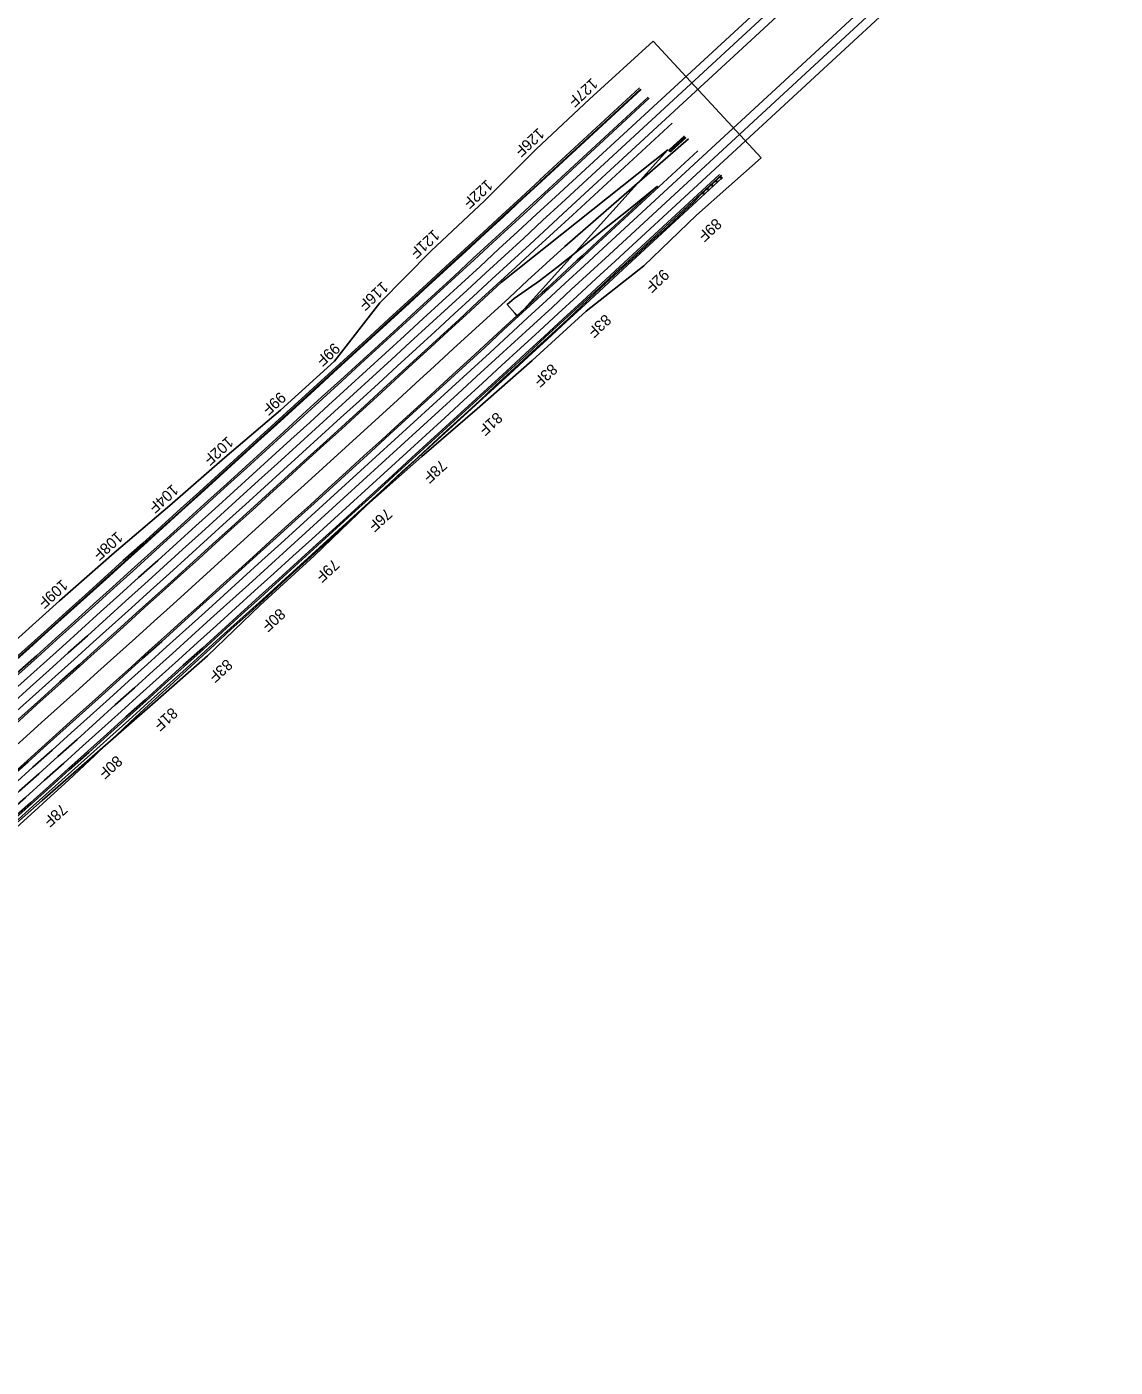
# Model space of a CAD drawing. Extents: x 2163396 to 2173129, y 605545 to 614595.
# Drawn here: x 2170912 to 2172401, y 611661 to 613496 of the extents above; entities that cross this region are included whole.
import ezdxf

# ---------------------------------------------------------------- set-up
doc = ezdxf.new("R2010")
doc.units = 0
for name, color, linetype in [('RD_PD_AsphRem', 7, 'Continuous'), ('RD_PD_CstnLmt', 7, 'Continuous'), ('RD_PD_EarthShd', 7, 'Continuous'), ('RD_PD_Final_LnLine', 7, 'Continuous'), ('RD_PD_Final_TrvlWay', 7, 'Continuous'), ('RD_PD_GR', 7, 'Continuous'), ('RD_PD_MedBWall', 7, 'Continuous'), ('RD_PD_MedGR', 7, 'Continuous'), ('RD_PD_TX_CstnLmt', 7, 'Continuous')]:
    doc.layers.add(name, color=color, linetype=linetype)

msp = doc.modelspace()

# ---------------------------------------------------------------- linework, layer by layer
at = {"layer": 'RD_PD_AsphRem'}
for p, q in [((2171692.3, 613201.6), (2171774.8, 613277.7)), ((2171839.8, 613272.5), (2171724.9, 613166.3))]:
    msp.add_line(p, q, dxfattribs=at)
for points in [[(2171774.8, 613277.7), (2171737.4, 613247.4), (2171702.4, 613219.4), (2171663.6, 613187.6), (2171637.1, 613166.7), (2171613.5, 613148.4), (2171579, 613124), (2171569.3, 613115.9), (2171579.5, 613104.1), (2171582.6, 613100.5)], [(2171211.3, 612689), (2171235.6, 612711.2), (2171254.9, 612729.1), (2171272, 612744.9), (2171294.8, 612765.6), (2171316.7, 612785.6), (2171342.8, 612809.8), (2171371.3, 612835.8), (2171400.7, 612863.9), (2171425.5, 612887.2), (2171446.8, 612906.6), (2171468, 612926.1), (2171487.3, 612943.9), (2171510.2, 612964.8), (2171531.3, 612984.1), (2171553.3, 613005.1), (2171579.8, 613029.1), (2171609.9, 613057), (2171645.3, 613089.3), (2171670.6, 613113), (2171698.2, 613139.5), (2171727.2, 613166.1), (2171745.1, 613182.7), (2171766.4, 613201.9), (2171788.8, 613222.3), (2171812.4, 613244.7), (2171824, 613255.6), (2171834.4, 613266.4), (2171839.8, 613272.5)], [(2170897.7, 612400.1), (2170922.2, 612422.5), (2170939.1, 612437.7), (2170968.6, 612464.9), (2170983.3, 612478.6), (2171004.7, 612498.6), (2171020.7, 612514), (2171034.6, 612526.4), (2171053.2, 612544), (2171078.9, 612567.8), (2171107.2, 612593.3), (2171131.4, 612615.9), (2171168.6, 612649.9), (2171191.6, 612671.6), (2171211.3, 612689)]]:
    msp.add_lwpolyline(points, dxfattribs=at)
for radius, start in [(73024, 312.60244), (73072, 310.953509)]:
    msp.add_arc((2122152.2, 666851.2), radius, start, 312.719474, dxfattribs=at)
at = {"layer": 'RD_PD_CstnLmt'}
for p, q in [((2171769.1, 613476.5), (2171681.8, 613396.8)), ((2171916.8, 613316.6), (2171769.1, 613476.5)), ((2171681.8, 613396.8), (2171608.7, 613328.5)), ((2171608.7, 613328.5), (2171538, 613257.8)), ((2171916.8, 613316.6), (2171828.3, 613238.1)), ((2171538, 613257.8), (2171465.3, 613189.4)), ((2171828.3, 613238.1), (2171756.3, 613168.6)), ((2171465.3, 613189.4), (2171395.1, 613118.2)), ((2171756.3, 613168.6), (2171677.2, 613106.8)), ((2171395.1, 613118.2), (2171333, 613038.3)), ((2171677.2, 613106.8), (2171603.4, 613039.1)), ((2171333, 613038.3), (2171259, 612971.2)), ((2171603.4, 613039.1), (2171528.3, 612972.9)), ((2171259, 612971.2), (2171183, 612906.3)), ((2171528.3, 612972.9), (2171452.3, 612907.7)), ((2171183, 612906.3), (2171107.7, 612840.7)), ((2171452.3, 612907.7), (2171377.3, 612841.4)), ((2171107.7, 612840.7), (2171031.5, 612776.1)), ((2171377.3, 612841.4), (2171305.2, 612771.9)), ((2171031.5, 612776.1), (2170956.3, 612710.4)), ((2171305.2, 612771.9), (2171231.3, 612704.4)), ((2170956.3, 612710.4), (2170882.2, 612643.4)), ((2171231.3, 612704.4), (2171159, 612635)), ((2171159, 612635), (2171083.9, 612568.8)), ((2171083.9, 612568.8), (2171008.3, 612503.2)), ((2171008.3, 612503.2), (2170933, 612437.1)), ((2170933, 612437.1), (2170857.7, 612371.2))]:
    msp.add_line(p, q, dxfattribs=at)
at = {"layer": 'RD_PD_EarthShd'}
for p, q in [((2171750.5, 613412.3), (2171614.1, 613286.3)), ((2171789.3, 613327.7), (2171561.6, 613146.4)), ((2171789.3, 613327.7), (2171592.3, 613109.4)), ((2171863.8, 613289.5), (2171727.4, 613163.6))]:
    msp.add_line(p, q, dxfattribs=at)
for radius, end in [(72908.7, 312.719474), (73075.8, 312.719474), (72976, 312.614643), (73024, 312.612747)]:
    msp.add_arc((2122152.2, 666851.2), radius, 310.953509, end, dxfattribs=at)
at = {"layer": 'RD_PD_Final_LnLine'}
for p, q in [((2172328.1, 613903), (2171635.3, 613263.3)), ((2172336.2, 613894.2), (2171643.5, 613254.5)), ((2172344.4, 613885.4), (2171651.6, 613245.7)), ((2172393.2, 613832.5), (2171700.5, 613192.8)), ((2172401.4, 613823.6), (2171708.6, 613184)), ((2172255.3, 613672.4), (2171716.8, 613175.1)), ((2171752.5, 613410.1), (2171616.1, 613284.1)), ((2171762, 613399.8), (2171625.6, 613273.8))]:
    msp.add_line(p, q, dxfattribs=at)
for radius in [72911.7, 72925.7, 72940, 72952, 72964, 73036, 73048, 73060]:
    msp.add_arc((2122152.2, 666851.2), radius, 310.953509, 312.719474, dxfattribs=at)
at = {"layer": 'RD_PD_Final_TrvlWay'}
for p, q in [((2171751.8, 613410.8), (2171615.4, 613284.9)), ((2171794.8, 613364.3), (2171658.4, 613238.3)), ((2171830.1, 613326.1), (2171693.7, 613200.1)), ((2171859.9, 613293.8), (2171723.5, 613167.8))]:
    msp.add_line(p, q, dxfattribs=at)
for radius in [72910.7, 72974, 73026, 73070]:
    msp.add_arc((2122152.2, 666851.2), radius, 310.953509, 312.719474, dxfattribs=at)
at = {"layer": 'RD_PD_GR'}
for p, q in [((2171648.1, 613195.4), (2171817.5, 613342.5)), ((2171862, 613293), (2171834.8, 613267.9)), ((2171835.2, 613267.5), (2171862.4, 613292.6)), ((2171848, 613279.3), (2171849.3, 613280.5)), ((2171849.4, 613277.9), (2171848, 613279.3)), ((2171849.3, 613280.5), (2171850.7, 613279.1)), ((2171850.7, 613279.1), (2171849.4, 613277.9)), ((2171850, 613278.5), (2171850.9, 613277.6)), ((2171850.2, 613277), (2171851.5, 613278.1)), ((2171853.9, 613284.8), (2171855.2, 613286)), ((2171855.3, 613283.3), (2171853.9, 613284.8)), ((2171855.2, 613286), (2171856.5, 613284.5)), ((2171856.5, 613284.5), (2171855.3, 613283.3)), ((2171855.9, 613283.9), (2171856.7, 613283)), ((2171856.1, 613282.4), (2171857.4, 613283.6)), ((2171859.8, 613290.2), (2171861.1, 613291.4)), ((2171861.1, 613288.7), (2171859.8, 613290.2)), ((2171861.1, 613291.4), (2171862.4, 613289.9)), ((2171862.4, 613289.9), (2171861.1, 613288.7)), ((2171861.8, 613289.3), (2171862.6, 613288.4)), ((2171862.4, 613292.6), (2171862, 613293)), ((2171862, 613287.8), (2171863.3, 613289)), ((2171834.8, 613267.9), (2171724.9, 613166.3)), ((2171834.8, 613267.9), (2171835.2, 613267.5)), ((2171836.3, 613268.5), (2171837.6, 613269.7)), ((2171837.6, 613267), (2171836.3, 613268.5)), ((2171837.6, 613269.7), (2171838.9, 613268.2)), ((2171838.9, 613268.2), (2171837.6, 613267)), ((2171838.3, 613267.6), (2171839.1, 613266.7)), ((2171838.5, 613266.1), (2171839.8, 613267.3)), ((2171839.9, 613271.8), (2171839.5, 613272.2)), ((2171842.1, 613273.9), (2171843.4, 613275.1)), ((2171843.5, 613272.4), (2171842.1, 613273.9)), ((2171843.4, 613275.1), (2171844.8, 613273.6)), ((2171844.8, 613273.6), (2171843.5, 613272.4)), ((2171844.1, 613273), (2171845, 613272.1)), ((2171844.4, 613271.5), (2171845.6, 613272.7))]:
    msp.add_line(p, q, dxfattribs=at)
for radius, end in [(72998.5, 312.690672), (73072, 312.719474)]:
    msp.add_arc((2122152.2, 666851.2), radius, 310.953509, end, dxfattribs=at)
at = {"layer": 'RD_PD_MedBWall'}
for p, q in [((2171762, 613399.8), (2171625.6, 613273.8)), ((2171763.6, 613398.1), (2171627.2, 613272.1))]:
    msp.add_line(p, q, dxfattribs=at)
for radius in [72925.7, 72928]:
    msp.add_arc((2122152.2, 666851.2), radius, 310.953509, 312.719474, dxfattribs=at)
at = {"layer": 'RD_PD_MedGR'}
for p, q in [((2171811.3, 613346.4), (2171791.5, 613328.1)), ((2171811.3, 613346.4), (2171791.5, 613328.1)), ((2171808.7, 613343.3), (2171791.8, 613327.7)), ((2171810.3, 613341.6), (2171793.4, 613326)), ((2171813.6, 613344), (2171793.7, 613325.6)), ((2171793.7, 613325.6), (2171813.6, 613344)), ((2171794, 613329.8), (2171795.9, 613331.5)), ((2171795.9, 613331.5), (2171796.2, 613331.8)), ((2171797.5, 613329.8), (2171795.9, 613331.5)), ((2171796.2, 613331.8), (2171798.1, 613333.6)), ((2171797.8, 613330.1), (2171796.2, 613331.8)), ((2171798.1, 613333.6), (2171798.4, 613333.8)), ((2171799.7, 613331.8), (2171798.1, 613333.6)), ((2171798.4, 613333.8), (2171800.3, 613335.6)), ((2171800, 613332.1), (2171798.4, 613333.8)), ((2171800.3, 613335.6), (2171800.6, 613335.9)), ((2171801.9, 613333.9), (2171800.3, 613335.6)), ((2171800.6, 613335.9), (2171802.5, 613337.6)), ((2171802.2, 613334.1), (2171800.6, 613335.9)), ((2171802.5, 613337.6), (2171802.8, 613337.9)), ((2171804.1, 613335.9), (2171802.5, 613337.6)), ((2171802.8, 613337.9), (2171804.7, 613339.7)), ((2171804.4, 613336.2), (2171802.8, 613337.9)), ((2171804.7, 613339.7), (2171805, 613339.9)), ((2171806.3, 613337.9), (2171804.7, 613339.7)), ((2171805, 613339.9), (2171807, 613341.7)), ((2171806.6, 613338.2), (2171805, 613339.9)), ((2171807, 613341.7), (2171807.2, 613342)), ((2171808.5, 613340), (2171807, 613341.7)), ((2171807.2, 613342), (2171808.7, 613343.3)), ((2171808.8, 613340.3), (2171807.2, 613342)), ((2171811.7, 613346), (2171808.7, 613343.3)), ((2171808.7, 613343.3), (2171811.7, 613346)), ((2171810.3, 613341.6), (2171808.7, 613343.3)), ((2171813.2, 613344.3), (2171810.3, 613341.6)), ((2171813.2, 613344.3), (2171810.3, 613341.6)), ((2171811.3, 613346.4), (2171811.7, 613346)), ((2171811.7, 613346), (2171811.3, 613346.4)), ((2171813.6, 613344), (2171813.2, 613344.3)), ((2171813.6, 613344), (2171813.2, 613344.3)), ((2171793.7, 613325.6), (2171791.5, 613328.1)), ((2171791.8, 613327.8), (2171791.5, 613328.1)), ((2171793.7, 613325.6), (2171793.5, 613325.9)), ((2171795.3, 613327.8), (2171793.7, 613329.5)), ((2171795.6, 613328), (2171794, 613329.8))]:
    msp.add_line(p, q, dxfattribs=at)
for points in [[(2171810.3, 613341.6), (2171808.8, 613340.3), (2171808.5, 613340), (2171806.6, 613338.2), (2171806.3, 613337.9), (2171804.4, 613336.2), (2171804.1, 613335.9), (2171802.2, 613334.1), (2171801.9, 613333.9), (2171800, 613332.1), (2171799.7, 613331.8), (2171797.8, 613330.1), (2171797.5, 613329.8), (2171795.6, 613328), (2171795.3, 613327.8), (2171793.4, 613326)], [(2171791.5, 613328.1), (2171791.8, 613327.8), (2171791.8, 613327.7)], [(2171791.8, 613327.7), (2171793.7, 613329.5), (2171794, 613329.8)], [(2171793.4, 613326), (2171793.5, 613325.9), (2171793.7, 613325.6)]]:
    msp.add_lwpolyline(points, dxfattribs=at)
for radius in [1.67, 1.67, 1.27, 1.27]:
    msp.add_arc((2171792.6, 613326.9), radius, 132.7195, 312.7195, dxfattribs=at)

# ---------------------------------------------------------------- texts
at = {"layer": 'RD_PD_TX_CstnLmt'}
for s, rotation, p in [('127F', 222.7195, (2171684.9, 613426.8)), ('126F', 222.7195, (2171611.8, 613358.6)), ('122F', 222.6603, (2171541.1, 613287.9)), ('89F', 222.7195, (2171854.3, 613235)), ('121F', 222.5819, (2171468.5, 613219.5)), ('92F', 222.7195, (2171782.4, 613165.4)), ('116F', 222.5034, (2171398.3, 613148.3)), ('83F', 222.6603, (2171703.2, 613103.6)), ('99F', 222.4249, (2171332, 613064.5)), ('83F', 222.5819, (2171629.5, 613035.9)), ('99F', 222.3464, (2171258, 612997.4)), ('81F', 222.5034, (2171554.4, 612969.6)), ('102F', 222.2679, (2171186.3, 612936.3)), ('78F', 222.4249, (2171478.3, 612904.4)), ('104F', 222.1894, (2171111, 612870.8)), ('76F', 222.3464, (2171403.3, 612838)), ('108F', 222.1109, (2171034.9, 612806.1)), ('79F', 222.2679, (2171331.2, 612768.5)), ('109F', 222.0324, (2170959.7, 612740.4)), ('80F', 222.1894, (2171257.3, 612701)), ('83F', 222.1109, (2171185, 612631.6)), ('81F', 222.0324, (2171109.9, 612565.3)), ('80F', 221.954, (2171034.3, 612499.6)), ('78F', 221.8755, (2170959, 612433.6))]:
    msp.add_text(s, height=15, rotation=rotation, dxfattribs=at).set_placement(p)

doc.saveas('drawing.dxf')
